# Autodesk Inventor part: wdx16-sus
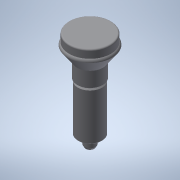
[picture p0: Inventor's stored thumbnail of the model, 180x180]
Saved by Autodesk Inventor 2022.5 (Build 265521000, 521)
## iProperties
Created: 2016-12
Part Number: wdx16-sus
Material: 一般
Document SubType Name: Modeling
Designer: imaocorp
Density: 1 g/cm^3
Appearance: 既定
Author: imaocorp
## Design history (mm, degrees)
node "wdx16-sus.x_t1"
node "wdx16-sus"
node "Base1"
